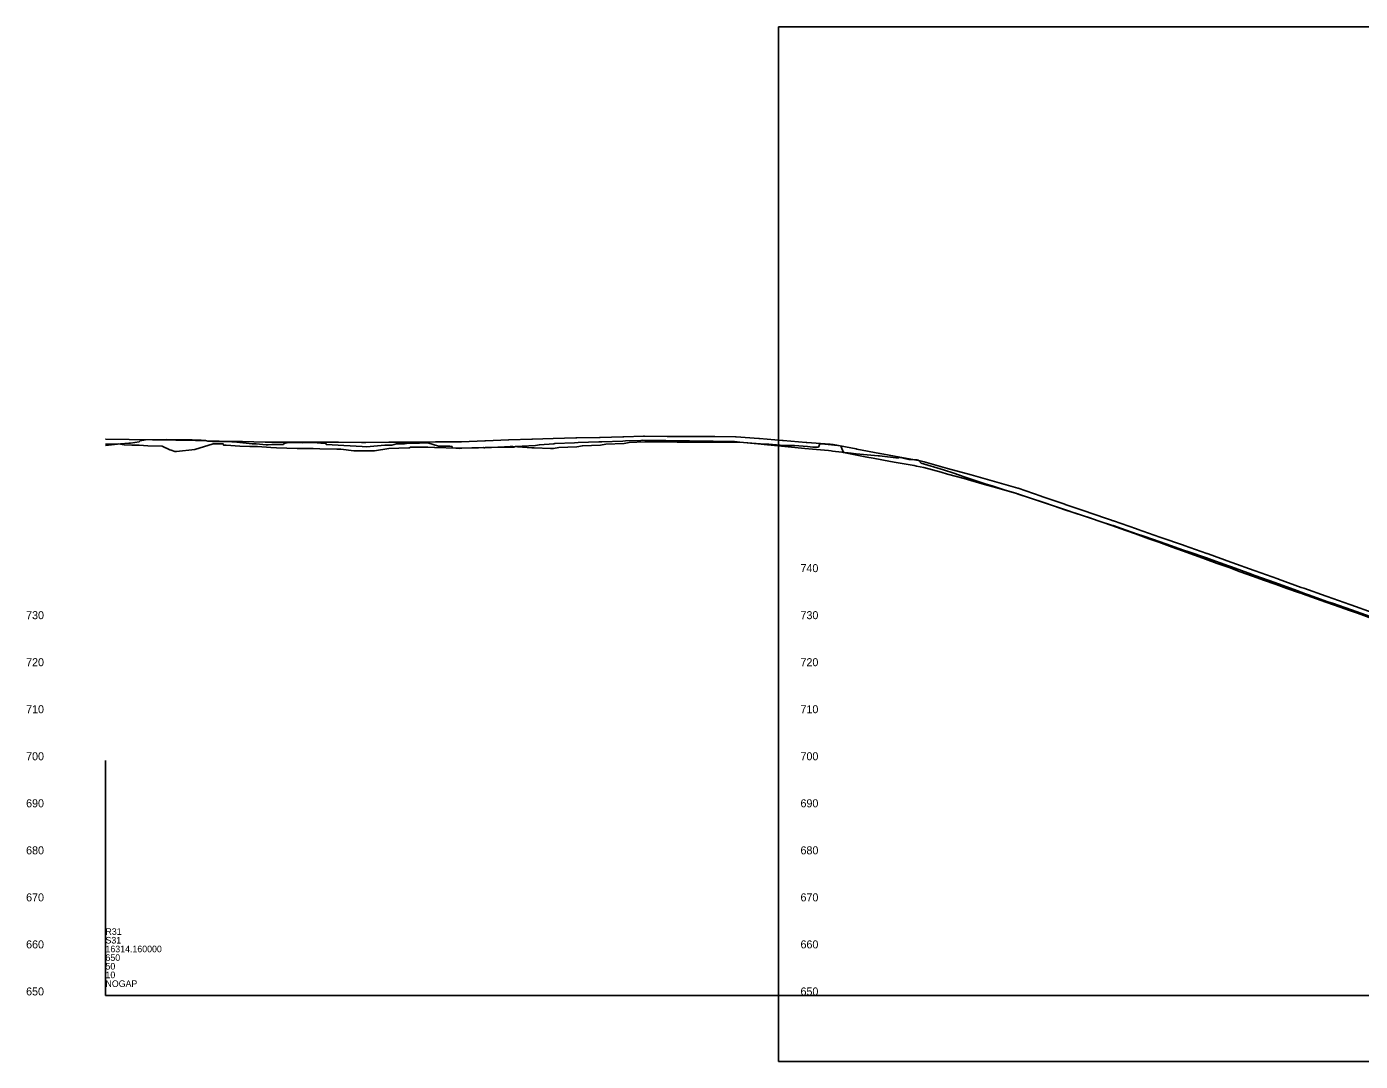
# Model space of a CAD drawing. Extents: x 1741783 to 1745041, y 1152835 to 1153935.
# Drawn here: x 1741783 to 1743200, y 1152835 to 1153935 of the extents above; entities that cross this region are included whole.
import ezdxf

# ---------------------------------------------------------------- set-up
doc = ezdxf.new("R2010")
doc.units = 0
for name, color, linetype in [('BR_EXIST_GROUND_LT', 7, 'Continuous'), ('BR_EXIST_GROUND_RT', 7, 'Continuous'), ('GN_Clip', 7, 'Continuous'), ('RD_DDB_ElevTX', 7, 'Continuous'), ('RD_DDB_Profile_EX', 7, 'Continuous'), ('RD_GPK_Profile_Cell', 7, 'Continuous')]:
    doc.layers.add(name, color=color, linetype=linetype)

msp = doc.modelspace()

# ---------------------------------------------------------------- linework, layer by layer
at = {"layer": 'BR_EXIST_GROUND_LT'}
msp.add_lwpolyline([(1741866.9, 1153491.5), (1741880.6, 1153491.8), (1741886.8, 1153491), (1741894.9, 1153490.6), (1741902.7, 1153490.4), (1741912, 1153489.8), (1741927.2, 1153489.5), (1741935.4, 1153485.4), (1741936.7, 1153485.3), (1741940.5, 1153483.8), (1741942.3, 1153483.8), (1741961.8, 1153485.9), (1741981.4, 1153491.8), (1741992, 1153491.8), (1741992.3, 1153490.4), (1741995.1, 1153490.4), (1742009.6, 1153489.4), (1742020.1, 1153489.1), (1742028.4, 1153488.9), (1742042.7, 1153487.9), (1742048.7, 1153487.5), (1742059.7, 1153487.4), (1742070.4, 1153487), (1742087.4, 1153486.9), (1742094.5, 1153486.5), (1742112.7, 1153486.3), (1742116.9, 1153486.1), (1742130.6, 1153484.4), (1742141.3, 1153484.3), (1742142.1, 1153484.3), (1742152.8, 1153484.3), (1742168, 1153486.8), (1742189.1, 1153487.7), (1742190, 1153487.5), (1742191.1, 1153488.2), (1742192, 1153488.2), (1742209.5, 1153488.2), (1742216.4, 1153488.1), (1742216.9, 1153488), (1742240.6, 1153487.4), (1742241.9, 1153487.3), (1742244.2, 1153487.2), (1742268.2, 1153488), (1742269.1, 1153487.8), (1742269.9, 1153487.7), (1742291, 1153488.8), (1742294, 1153488.8), (1742296.7, 1153488.9), (1742297.4, 1153488.9), (1742299.8, 1153488.9), (1742320, 1153487.6), (1742322.3, 1153487.7), (1742339.8, 1153486.8), (1742342.8, 1153487.1), (1742348.6, 1153488.1), (1742367.8, 1153488.8), (1742373.6, 1153489.9), (1742392.8, 1153490.6), (1742398.5, 1153491.7), (1742417.8, 1153492.4), (1742423.1, 1153493.3), (1742440, 1153494), (1742446.9, 1153494), (1742464.9, 1153493.9), (1742474.1, 1153493.8), (1742489.9, 1153493.7), (1742502.4, 1153493.7), (1742514.8, 1153493.6), (1742532, 1153493.6), (1742537.9, 1153493.6), (1742544.9, 1153493.4), (1742562.9, 1153491.8), (1742571.8, 1153491.5), (1742587.8, 1153490.2), (1742599, 1153490), (1742612.8, 1153488.9), (1742618.3, 1153488.4), (1742624.4, 1153488.4), (1742625.9, 1153491.9), (1742626.6, 1153491.9), (1742627.4, 1153491.9), (1742631.1, 1153491.5), (1742645.1, 1153490.1), (1742647.4, 1153489.8), (1742647.8, 1153489.4), (1742648.5, 1153488.7), (1742650.9, 1153482.6), (1742658.1, 1153481.1), (1742675.9, 1153477.9), (1742682.6, 1153476.5), (1742700.9, 1153473.3), (1742707.1, 1153472), (1742725.9, 1153468.7), (1742728.5, 1153468.2), (1742736.4, 1153466.8), (1742754.9, 1153461.7), (1742761.3, 1153459.8), (1742779, 1153454.9), (1742786.3, 1153452.8), (1742803.2, 1153448.1), (1742811.3, 1153445.7), (1742827.5, 1153441.2), (1742836.3, 1153438.7), (1742836.8, 1153438.5), (1742851.7, 1153433.5), (1742861.8, 1153430.2), (1742875, 1153425.8), (1742886.7, 1153421.9), (1742898.3, 1153418), (1742911.7, 1153413.5), (1742921.7, 1153410.2), (1742936.7, 1153405.2), (1742937.3, 1153405), (1742946.3, 1153401.8), (1742962.3, 1153396.3), (1742970, 1153393.6), (1742987.3, 1153387.6), (1742993.5, 1153385.5), (1743012.3, 1153379), (1743016.9, 1153377.4), (1743037.6, 1153370.2), (1743038.3, 1153370), (1743060, 1153362.2), (1743063.2, 1153361), (1743084.6, 1153353.3), (1743088.1, 1153352), (1743109.2, 1153344.4), (1743113.1, 1153342.9), (1743133.8, 1153335.5), (1743138, 1153333.9), (1743138.4, 1153333.8), (1743140.8, 1153332.9), (1743145.1, 1153331.4), (1743165.7, 1153324.1), (1743170.4, 1153322.5), (1743190.7, 1153315.3), (1743195.6, 1153313.6), (1743215.6, 1153306.5)], dxfattribs=at)
at = {"layer": 'BR_EXIST_GROUND_RT'}
msp.add_lwpolyline([(1741867, 1153490.1), (1741882.9, 1153491.9), (1741891.8, 1153492.5), (1741893.4, 1153492.6), (1741902.8, 1153494.1), (1741903.6, 1153495.1), (1741909.4, 1153496.3), (1741931.4, 1153496.4), (1741933.3, 1153496.3), (1741936.8, 1153496.3), (1741956.3, 1153496.2), (1741959.1, 1153496.2), (1741968.5, 1153495.7), (1741973.2, 1153495.6), (1741975.7, 1153494.6), (1741980.7, 1153494.5), (1742001.1, 1153493.9), (1742002.1, 1153493.9), (1742006.4, 1153493.7), (1742022.7, 1153491.9), (1742027, 1153491.8), (1742037.7, 1153490.9), (1742039.8, 1153490.9), (1742043.7, 1153491.2), (1742055.9, 1153491.3), (1742056.5, 1153492.2), (1742059.8, 1153492.8), (1742062.4, 1153493.2), (1742076.6, 1153493.1), (1742085.7, 1153493.5), (1742087.8, 1153493.5), (1742095.7, 1153492.5), (1742100.8, 1153492.5), (1742101.6, 1153491.1), (1742120.3, 1153490), (1742126.7, 1153489.7), (1742139.6, 1153489), (1742144.3, 1153488.7), (1742163.8, 1153490.4), (1742169.1, 1153490.4), (1742171.3, 1153490.5), (1742176.2, 1153491.9), (1742184.7, 1153492), (1742188.9, 1153492.5), (1742200.6, 1153492.6), (1742209.4, 1153492.8), (1742220.8, 1153489.5), (1742232.7, 1153489.6), (1742235, 1153489.1), (1742235.7, 1153487.6), (1742242.6, 1153486.9), (1742245.4, 1153487.4), (1742263.3, 1153487.6), (1742270.3, 1153488), (1742273.5, 1153488.1), (1742294.2, 1153488.4), (1742295.9, 1153488.4), (1742300.7, 1153488.4), (1742302.5, 1153488.9), (1742323.8, 1153490.2), (1742327.9, 1153491), (1742343.3, 1153492), (1742344.3, 1153492.2), (1742365.3, 1153492.9), (1742369.2, 1153493.2), (1742390.9, 1153493.9), (1742394.2, 1153494.1), (1742416.5, 1153494.9), (1742419.2, 1153495.1), (1742435.7, 1153495.6), (1742437.3, 1153495.7), (1742459.8, 1153495.4), (1742462.3, 1153495.4), (1742484.2, 1153495.1), (1742487.4, 1153495), (1742508.4, 1153494.7), (1742512.4, 1153494.6), (1742530.8, 1153494.4), (1742535, 1153494.3), (1742540.9, 1153493.8), (1742560, 1153491.9), (1742566.6, 1153491.3), (1742585, 1153489.4), (1742592.3, 1153488.8), (1742610, 1153487), (1742618, 1153486.4), (1742635, 1153484.7), (1742637.8, 1153484.4), (1742639.3, 1153484.2), (1742659.3, 1153482.1), (1742664.3, 1153481.4), (1742687.7, 1153479.2), (1742689.4, 1153479), (1742709.3, 1153476.7), (1742709.6, 1153477.8), (1742720.5, 1153475.4), (1742729.1, 1153474.8), (1742730.5, 1153474.5), (1742733.6, 1153471.5), (1742757.2, 1153464.2), (1742758.4, 1153463.9), (1742767, 1153461.2), (1742780.4, 1153456.4), (1742783.5, 1153455.5), (1742801.4, 1153449.3), (1742808.8, 1153447.2), (1742822.7, 1153442.5), (1742834.1, 1153439.3), (1742835.8, 1153438.7), (1742836.4, 1153438.5), (1742849.8, 1153434.1), (1742861.4, 1153430.2), (1742875.2, 1153425.6), (1742886.3, 1153421.9), (1742900.5, 1153417.1), (1742911.3, 1153413.5), (1742925.9, 1153408.6), (1742936.2, 1153405.2), (1742950.9, 1153399.8), (1742961.1, 1153396.2), (1742975.5, 1153391), (1742986, 1153387.2), (1743000, 1153382.2), (1743011, 1153378.2), (1743024, 1153373.5), (1743035.7, 1153369.3), (1743047.9, 1153364.8), (1743060.7, 1153360.3), (1743072.5, 1153356), (1743085.6, 1153351.3), (1743097.2, 1153347.1), (1743110.6, 1153342.4), (1743121.9, 1153338.2), (1743135.5, 1153333.4), (1743136.7, 1153333), (1743138.5, 1153332.3), (1743148.6, 1153328.9), (1743163.5, 1153323.5), (1743172.6, 1153320.4), (1743188.5, 1153314.7), (1743196.9, 1153311.8), (1743213.5, 1153305.8)], dxfattribs=at)
at = {"layer": 'GN_Clip'}
for p, q in [((1742582, 1153935.4), (1744382, 1153935.4)), ((1742582, 1152835.4), (1742582, 1153935.4)), ((1744382, 1152835.4), (1742582, 1152835.4))]:
    msp.add_line(p, q, dxfattribs=at)
at = {"layer": 'RD_DDB_Profile_EX'}
msp.add_lwpolyline([(1741866.9, 1153496.9), (1741867.3, 1153496.9), (1741891.9, 1153496.5), (1741892.2, 1153496.5), (1741916.7, 1153496.1), (1741917.2, 1153496.1), (1741941.8, 1153495.7), (1741942.4, 1153495.7), (1741962.4, 1153495.3), (1741986.6, 1153494.8), (1741987.6, 1153494.8), (1742011.8, 1153494.3), (1742012.6, 1153494.3), (1742036.7, 1153493.8), (1742037.4, 1153493.8), (1742039.5, 1153493.8), (1742063.6, 1153493.7), (1742064.5, 1153493.7), (1742088.7, 1153493.6), (1742089.5, 1153493.6), (1742113.8, 1153493.6), (1742114.5, 1153493.6), (1742138.8, 1153493.5), (1742139.5, 1153493.5), (1742142.8, 1153493.5), (1742143.4, 1153493.5), (1742167.8, 1153493.7), (1742168.3, 1153493.7), (1742192.8, 1153493.8), (1742217.4, 1153494), (1742217.8, 1153494), (1742242.4, 1153494.2), (1742242.8, 1153494.2), (1742244.9, 1153494.2), (1742245.3, 1153494.2), (1742269.9, 1153495.1), (1742270.5, 1153495.1), (1742294.9, 1153496), (1742295.6, 1153496), (1742319.9, 1153496.9), (1742320.7, 1153496.9), (1742342.5, 1153497.7), (1742366.5, 1153498.2), (1742367.5, 1153498.3), (1742391.6, 1153498.8), (1742392.5, 1153498.8), (1742416.6, 1153499.4), (1742417.5, 1153499.4), (1742438.6, 1153499.9), (1742439.4, 1153499.9), (1742463.5, 1153499.8), (1742464.4, 1153499.8), (1742488.5, 1153499.7), (1742489.4, 1153499.7), (1742513.5, 1153499.6), (1742514.4, 1153499.6), (1742536.1, 1153499.5), (1742536.9, 1153499.5), (1742561.1, 1153497.5), (1742561.9, 1153497.5), (1742586.1, 1153495.5), (1742586.9, 1153495.4), (1742611.2, 1153493.5), (1742612.2, 1153493.4), (1742636.5, 1153491.4), (1742637, 1153491.3), (1742639.8, 1153491.1), (1742640.1, 1153491.1), (1742664.5, 1153486.5), (1742665, 1153486.4), (1742689.6, 1153481.7), (1742689.9, 1153481.7), (1742714.8, 1153477), (1742732.3, 1153473.7), (1742736.6, 1153472.9), (1742744.2, 1153470.7), (1742761.5, 1153465.8), (1742786.5, 1153458.8), (1742811.5, 1153451.7), (1742836.1, 1153444.7), (1742836.6, 1153444.6), (1742861.1, 1153436.2), (1742861.6, 1153436), (1742886, 1153427.7), (1742886.5, 1153427.5), (1742910.9, 1153419.2), (1742911.5, 1153419), (1742935.7, 1153410.7), (1742936.4, 1153410.4), (1742937.3, 1153410.1), (1742938, 1153409.9), (1742962.2, 1153401.4), (1742963, 1153401.2), (1742987.2, 1153392.7), (1742988, 1153392.5), (1743012.1, 1153384), (1743013, 1153383.7), (1743037.1, 1153375.3), (1743037.5, 1153375.2), (1743038.4, 1153374.8), (1743062.4, 1153366.2), (1743063.4, 1153365.9), (1743087.3, 1153357.3), (1743088.3, 1153356.9), (1743112.3, 1153348.3), (1743113.3, 1153348), (1743137.2, 1153339.3), (1743139.9, 1153338.4), (1743163.9, 1153329.9), (1743164.9, 1153329.6), (1743188.8, 1153321.1), (1743189.8, 1153320.8), (1743213.8, 1153312.3)], dxfattribs=at)
at = {"layer": 'RD_GPK_Profile_Cell'}
for q in [(1741866.9, 1153155.3), (1745041.2, 1152905.3), (1741866.9, 1152905.3)]:
    msp.add_line((1741866.9, 1152905.3), q, dxfattribs=at)

# ---------------------------------------------------------------- texts
at = {"layer": 'RD_DDB_ElevTX'}
for s, p in [('740', (1742605.3, 1153355.5)), ('730', (1741782.6, 1153305.5)), ('730', (1742605.3, 1153305.5)), ('720', (1741782.6, 1153255.5)), ('720', (1742605.3, 1153255.5)), ('710', (1741782.6, 1153205.5)), ('710', (1742605.3, 1153205.5)), ('700', (1741782.6, 1153155.5)), ('700', (1742605.3, 1153155.5)), ('690', (1741782.6, 1153105.5)), ('690', (1742605.3, 1153105.5)), ('680', (1741782.6, 1153055.5)), ('680', (1742605.3, 1153055.5)), ('670', (1741782.6, 1153005.5)), ('670', (1742605.3, 1153005.5)), ('660', (1741782.6, 1152955.5)), ('660', (1742605.3, 1152955.5)), ('650', (1741782.6, 1152905.5)), ('650', (1742605.3, 1152905.5))]:
    msp.add_text(s, height=8.5, dxfattribs=at).set_placement(p)
at = {"layer": 'RD_GPK_Profile_Cell'}
for s, p in [('R31', (1741866.9, 1152969.9)), ('S31', (1741866.9, 1152960.7)), ('16314.160000', (1741866.9, 1152951.4)), ('650', (1741866.9, 1152942.2)), ('50', (1741866.9, 1152933)), ('10', (1741866.9, 1152923.8)), ('NOGAP', (1741866.9, 1152914.5))]:
    msp.add_text(s, height=7, dxfattribs=at).set_placement(p)

doc.saveas('drawing.dxf')
